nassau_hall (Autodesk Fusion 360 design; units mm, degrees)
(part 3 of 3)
sketch "Sketch80" plane through (0, 0, -14.3624) normal (0, 0, -1) x axis (1, 0, 0)
  line L1 (-39, 78) -> (-39, 61)
  line L2 (32, 78) -> (-39, 78)
  line L3 (32, 61) -> (32, 78)
  line L4 (33.9524, 61) -> (32, 61)
  line L5 (33.9524, 61.1302) -> (33.9524, 61)
  line L6 (157.9638, 61.1302) -> (33.9524, 61.1302)
  line L7 (157.9638, -17.1616) -> (157.9638, 61.1302)
  line L8 (33.9524, -17.1616) -> (157.9638, -17.1616)
  line L9 (33.9524, -17.0793) -> (33.9524, -17.1616)
  line L10 (32, -17.0793) -> (33.9524, -17.0793)
  line L11 (32, -55.6025) -> (32, -17.0793)
  line L12 (-38.959, -55.6025) -> (32, -55.6025)
  line L13 (-38.959, -19) -> (-38.959, -55.6025)
  line L14 (-39.0985, -19) -> (-38.959, -19)
  line L15 (-39.0985, -17.0793) -> (-39.0985, -19)
  line L16 (-41.0476, -17.0793) -> (-39.0985, -17.0793)
  line L17 (-41.0476, -57.3945) -> (-41.0476, -17.0793)
  line L18 (33.9524, -57.3945) -> (-41.0476, -57.3945)
  line L19 (33.9524, -32.3945) -> (33.9524, -57.3945)
  line L20 (160.4524, -32.3945) -> (33.9524, -32.3945)
  line L21 (160.4524, 63.1055) -> (160.4524, -32.3945)
  line L22 (33.9524, 63.1055) -> (160.4524, 63.1055)
  line L23 (33.9524, 80.1055) -> (33.9524, 63.1055)
  line L24 (-41.0476, 80.1055) -> (33.9524, 80.1055)
  line L25 (-41.0476, 61) -> (-41.0476, 80.1055)
  line L26 (-39, 61) -> (-41.0476, 61)
  line L27 (33.9524, -17.0793) -> (32, -17.0793)
  line L28 (33.9524, -30.8511) -> (33.9524, -17.0793)
  line L29 (32, -30.8511) -> (33.9524, -30.8511)
  line L30 (32, -17.0793) -> (32, -30.8511)
  point P12 (32, -17.0793)
  point P28 (32, -17.0793)
  horizontal L27
  vertical L28
  horizontal L29
  vertical L30
  coincident P12 P28
extrude "Extrude54" cut sketch "Sketch80" profile of L9 L10 L11 L27 L28 L29 L30 against normal blind 70
sketch "Sketch81" plane through (0, 0, -14.3624) normal (0, 0, -1) x axis (1, 0, 0)
  line L1 (32, -30.8511) -> (33.9524, -30.8511)
  line L2 (32, -55.6025) -> (32, -30.8511)
  line L3 (-38.959, -55.6025) -> (32, -55.6025)
  line L4 (-38.959, -19) -> (-38.959, -55.6025)
  line L5 (-39.0985, -19) -> (-38.959, -19)
  line L6 (-39.0985, -17.0793) -> (-39.0985, -19)
  line L7 (-41.0476, -17.0793) -> (-39.0985, -17.0793)
  line L8 (-41.0476, -57.3945) -> (-41.0476, -17.0793)
  line L9 (33.9524, -57.3945) -> (-41.0476, -57.3945)
  line L10 (33.9524, -32.3945) -> (33.9524, -57.3945)
  line L11 (160.4524, -32.3945) -> (33.9524, -32.3945)
  line L12 (160.4524, 63.1055) -> (160.4524, -32.3945)
  line L13 (33.9524, 63.1055) -> (160.4524, 63.1055)
  line L14 (33.9524, 80.1055) -> (33.9524, 63.1055)
  line L15 (-41.0476, 80.1055) -> (33.9524, 80.1055)
  line L16 (-41.0476, 61) -> (-41.0476, 80.1055)
  line L17 (-39, 61) -> (-41.0476, 61)
  line L18 (-39, 78) -> (-39, 61)
  line L19 (32, 78) -> (-39, 78)
  line L20 (32, 61) -> (32, 78)
  line L21 (33.9524, 61) -> (32, 61)
  line L22 (33.9524, 61.1302) -> (33.9524, 61)
  line L23 (157.9638, 61.1302) -> (33.9524, 61.1302)
  line L24 (157.9638, -17.1616) -> (157.9638, 61.1302)
  line L25 (33.9524, -17.1616) -> (157.9638, -17.1616)
  line L26 (33.9524, -30.8511) -> (33.9524, -17.1616)
  line L27 (157.9638, -30.8511) -> (33.9524, -30.8511)
  line L28 (157.9638, -17.1616) -> (157.9638, -30.8511)
  line L29 (33.9524, -17.1616) -> (157.9638, -17.1616)
  line L30 (33.9524, -30.8511) -> (33.9524, -17.1616)
  point P26 (157.9638, -17.1616)
  point P30 (157.9638, -17.1616)
  point P2 (33.9524, -30.8511)
  point P28 (33.9524, -30.8511)
  horizontal L27
  vertical L28
  horizontal L29
  vertical L30
  coincident P26 P30
  coincident P2 P28
extrude "Extrude55" cut sketch "Sketch81" profile of L25 L26 L27 L28 L29 L30 against normal blind 70
extrude "Extrude56" add of existing geometry blind 12
sketch "Sketch82" plane through (0, 0, -14.3624) normal (0, 0, -1) x axis (1, 0, 0)
  line L1 (-39, 61) -> (-166, 61)
  line L2 (-39, 78) -> (-39, 61)
  line L3 (32, 78) -> (-39, 78)
  line L4 (32, 61) -> (32, 78)
  line L5 (33.9524, 61) -> (32, 61)
  line L6 (33.9524, 61.1302) -> (33.9524, 61)
  line L7 (157.9638, 61.1302) -> (33.9524, 61.1302)
  line L8 (157.9638, -30.8511) -> (157.9638, 61.1302)
  line L9 (32, -30.8511) -> (157.9638, -30.8511)
  line L10 (32, -55.6025) -> (32, -30.8511)
  line L11 (-38.959, -55.6025) -> (32, -55.6025)
  line L12 (-38.959, -19) -> (-38.959, -55.6025)
  line L13 (-39.0985, -19) -> (-38.959, -19)
  line L14 (-39.0985, -17.0793) -> (-39.0985, -19)
  line L15 (-41.0476, -17.0793) -> (-39.0985, -17.0793)
  line L16 (-41.0476, -17.2714) -> (-41.0476, -17.0793)
  line L17 (-43, -17.2714) -> (-41.0476, -17.2714)
  line L18 (-43, -18) -> (-43, -17.2714)
  line L19 (-166, -18) -> (-43, -18)
  line L20 (-166, 61) -> (-166, -18)
  line L21 (-167.5476, 63.1055) -> (-41.0476, 63.1055)
  line L22 (-167.5476, -31.3945) -> (-167.5476, 63.1055)
  line L23 (-41.0476, -31.3945) -> (-167.5476, -31.3945)
  line L24 (-41.0476, -57.3945) -> (-41.0476, -31.3945)
  line L25 (33.9524, -57.3945) -> (-41.0476, -57.3945)
  line L26 (33.9524, -32.3945) -> (33.9524, -57.3945)
  line L27 (160.4524, -32.3945) -> (33.9524, -32.3945)
  line L28 (160.4524, 63.1055) -> (160.4524, -32.3945)
  line L29 (33.9524, 63.1055) -> (160.4524, 63.1055)
  line L30 (33.9524, 80.1055) -> (33.9524, 63.1055)
  line L31 (-41.0476, 80.1055) -> (33.9524, 80.1055)
  line L32 (-41.0476, 63.1055) -> (-41.0476, 80.1055)
  line L33 (-166, -18) -> (-43, -18)
  line L34 (-166, -30) -> (-166, -18)
  line L35 (-43, -30) -> (-166, -30)
  line L36 (-43, -18) -> (-43, -30)
  point P20 (-43, -18)
  point P34 (-43, -18)
  horizontal L33
  vertical L34
  horizontal L35
  vertical L36
  coincident P20 P34
extrude "Extrude57" cut sketch "Sketch82" profile of L19 L33 L34 L35 L36 against normal blind 70
sketch "Sketch83" plane through (0, 0, -14.3624) normal (0, 0, -1) x axis (1, 0, 0)
  line L1 (-167.5476, 63.1055) -> (-41.0476, 63.1055)
  line L2 (-167.5476, -31.3945) -> (-167.5476, 63.1055)
  line L3 (-41.0476, -31.3945) -> (-167.5476, -31.3945)
  line L4 (-41.0476, -57.3945) -> (-41.0476, -31.3945)
  line L5 (33.9524, -57.3945) -> (-41.0476, -57.3945)
  line L6 (33.9524, -32.3945) -> (33.9524, -57.3945)
  line L7 (160.4524, -32.3945) -> (33.9524, -32.3945)
  line L8 (160.4524, 63.1055) -> (160.4524, -32.3945)
  line L9 (33.9524, 63.1055) -> (160.4524, 63.1055)
  line L10 (33.9524, 80.1055) -> (33.9524, 63.1055)
  line L11 (-41.0476, 80.1055) -> (33.9524, 80.1055)
  line L12 (-41.0476, 63.1055) -> (-41.0476, 80.1055)
  line L13 (-43, -30) -> (-43, -17.2714)
  line L14 (-166, -30) -> (-43, -30)
  line L15 (-166, 61) -> (-166, -30)
  line L16 (-39, 61) -> (-166, 61)
  line L17 (-39, 78) -> (-39, 61)
  line L18 (32, 78) -> (-39, 78)
  line L19 (32, 61) -> (32, 78)
  line L20 (33.9524, 61) -> (32, 61)
  line L21 (33.9524, 61.1302) -> (33.9524, 61)
  line L22 (157.9638, 61.1302) -> (33.9524, 61.1302)
  line L23 (157.9638, -30.8511) -> (157.9638, 61.1302)
  line L24 (32, -30.8511) -> (157.9638, -30.8511)
  line L25 (32, -55.6025) -> (32, -30.8511)
  line L26 (-38.959, -55.6025) -> (32, -55.6025)
  line L27 (-38.959, -19) -> (-38.959, -55.6025)
  line L28 (-39.0985, -19) -> (-38.959, -19)
  line L29 (-39.0985, -17.0793) -> (-39.0985, -19)
  line L30 (-41.0476, -17.0793) -> (-39.0985, -17.0793)
  line L31 (-41.0476, -17.2714) -> (-41.0476, -17.0793)
  line L32 (-43, -17.2714) -> (-41.0476, -17.2714)
  line L33 (-39.0985, -17.0793) -> (-41.0476, -17.0793)
  line L34 (-39.0985, -30.309) -> (-39.0985, -17.0793)
  line L35 (-41.0476, -30.309) -> (-39.0985, -30.309)
  line L36 (-41.0476, -17.0793) -> (-41.0476, -30.309)
  point P32 (-41.0476, -17.0793)
  point P34 (-41.0476, -17.0793)
  horizontal L33
  vertical L34
  horizontal L35
  vertical L36
  coincident P32 P34
extrude "Extrude58" cut sketch "Sketch83" profile of L29 L30 L31 L33 L34 L35 L36 against normal blind 70
sketch "Sketch84" plane through (0, 0, -14.3624) normal (0, 0, -1) x axis (1, 0, 0)
  line L1 (-39.0985, -30.309) -> (-39.0985, -19)
  line L2 (-41.0476, -30.309) -> (-39.0985, -30.309)
  line L3 (-41.0476, -17.2714) -> (-41.0476, -30.309)
  line L4 (-43, -17.2714) -> (-41.0476, -17.2714)
  line L5 (-43, -30) -> (-43, -17.2714)
  line L6 (-166, -30) -> (-43, -30)
  line L7 (-166, 61) -> (-166, -30)
  line L8 (-39, 61) -> (-166, 61)
  line L9 (-39, 78) -> (-39, 61)
  line L10 (32, 78) -> (-39, 78)
  line L11 (32, 61) -> (32, 78)
  line L12 (33.9524, 61) -> (32, 61)
  line L13 (33.9524, 61.1302) -> (33.9524, 61)
  line L14 (157.9638, 61.1302) -> (33.9524, 61.1302)
  line L15 (157.9638, -30.8511) -> (157.9638, 61.1302)
  line L16 (32, -30.8511) -> (157.9638, -30.8511)
  line L17 (32, -55.6025) -> (32, -30.8511)
  line L18 (-38.959, -55.6025) -> (32, -55.6025)
  line L19 (-38.959, -19) -> (-38.959, -55.6025)
  line L20 (-39.0985, -19) -> (-38.959, -19)
  line L21 (-167.5476, 63.1055) -> (-41.0476, 63.1055)
  line L22 (-167.5476, -31.3945) -> (-167.5476, 63.1055)
  line L23 (-41.0476, -31.3945) -> (-167.5476, -31.3945)
  line L24 (-41.0476, -57.3945) -> (-41.0476, -31.3945)
  line L25 (33.9524, -57.3945) -> (-41.0476, -57.3945)
  line L26 (33.9524, -32.3945) -> (33.9524, -57.3945)
  line L27 (160.4524, -32.3945) -> (33.9524, -32.3945)
  line L28 (160.4524, 63.1055) -> (160.4524, -32.3945)
  line L29 (33.9524, 63.1055) -> (160.4524, 63.1055)
  line L30 (33.9524, 80.1055) -> (33.9524, 63.1055)
  line L31 (-41.0476, 80.1055) -> (33.9524, 80.1055)
  line L32 (-41.0476, 63.1055) -> (-41.0476, 80.1055)
  line L33 (-41.0476, -17.2714) -> (-43, -17.2714)
  line L34 (-41.0476, -30.0185) -> (-41.0476, -17.2714)
  line L35 (-43, -30.0185) -> (-41.0476, -30.0185)
  line L36 (-43, -17.2714) -> (-43, -30.0185)
  point P36 (-41.0476, -30.0185)
  point P6 (-43, -17.2714)
  point P34 (-43, -17.2714)
  horizontal L33
  vertical L34
  horizontal L35
  vertical L36
  coincident L3 P36
  coincident P6 P34
extrude "Extrude59" cut sketch "Sketch84" profile of L3 L4 L5 L33 L34 L35 L36 against normal blind 70
sketch "Sketch85" plane through (0, 0, 55.6376) normal (0, 0, -1) x axis (1, 0, 0)
  line L1 (-166, -30.2) -> (-38.9574, -30.3224)
  line L2 (-165.9998, -30.0065) -> (-166, -30.2)
  perpendicular L1 L2
sketch "Sketch86" plane through (0, 0, -14.3624) normal (0, 0, -1) x axis (1, 0, 0)
  line L1 (-167.5476, 63.1055) -> (-41.0476, 63.1055)
  line L2 (-167.5476, -31.3945) -> (-167.5476, 63.1055)
  line L3 (-41.0476, -31.3945) -> (-167.5476, -31.3945)
  line L4 (-41.0476, -57.3945) -> (-41.0476, -31.3945)
  line L5 (33.9524, -57.3945) -> (-41.0476, -57.3945)
  line L6 (33.9524, -32.3945) -> (33.9524, -57.3945)
  line L7 (160.4524, -32.3945) -> (33.9524, -32.3945)
  line L8 (160.4524, 63.1055) -> (160.4524, -32.3945)
  line L9 (33.9524, 63.1055) -> (160.4524, 63.1055)
  line L10 (33.9524, 80.1055) -> (33.9524, 63.1055)
  line L11 (-41.0476, 80.1055) -> (33.9524, 80.1055)
  line L12 (-41.0476, 63.1055) -> (-41.0476, 80.1055)
  line L13 (-43, -30.0185) -> (-41.0476, -30.0185)
  line L14 (-43, -30) -> (-43, -30.0185)
  line L15 (-166, -30) -> (-43, -30)
  line L16 (-166, 61) -> (-166, -30)
  line L17 (-39, 61) -> (-166, 61)
  line L18 (-39, 78) -> (-39, 61)
  line L19 (32, 78) -> (-39, 78)
  line L20 (32, 61) -> (32, 78)
  line L21 (33.9524, 61) -> (32, 61)
  line L22 (33.9524, 61.1302) -> (33.9524, 61)
  line L23 (157.9638, 61.1302) -> (33.9524, 61.1302)
  line L24 (157.9638, -30.8511) -> (157.9638, 61.1302)
  line L25 (32, -30.8511) -> (157.9638, -30.8511)
  line L26 (32, -55.6025) -> (32, -30.8511)
  line L27 (-38.959, -55.6025) -> (32, -55.6025)
  line L28 (-38.959, -19) -> (-38.959, -55.6025)
  line L29 (-39.0985, -19) -> (-38.959, -19)
  line L30 (-39.0985, -30.309) -> (-39.0985, -19)
  line L31 (-41.0476, -30.309) -> (-39.0985, -30.309)
  line L32 (-41.0476, -30.0185) -> (-41.0476, -30.309)
  line L33 (-39.0985, -30.309) -> (-38.959, -30.309)
  point P34 (-38.959, -30.309)
  point P32 (-39.0985, -30.309)
  point P35 (-39.0985, -30.309)
  coincident L28 P34
  coincident P32 P35
  perpendicular L30 L33
extrude "Extrude60" cut sketch "Sketch86" profile of L28 L29 L30 L33 against normal blind 70
sphere_primitive "SpherePrimitive5" Diameter 3
move_face "MoveFace17"
move_face "MoveFace18"
move_face "MoveFace19"
move "Move34"
move "Move35"
move "Move36"
move_face "MoveFace20"
move "Move37"
move "Move38"
move_face "MoveFace21"
offset_faces "OffsetFaces1" distance -0.5
delete_face "DeleteFace6"
combine "Combine1"
extrude "Extrude61" add of existing geometry blind 3
extrude "Extrude62" add of existing geometry blind 4
extrude "Extrude63" add of existing geometry blind 7
extrude "Extrude64" add sketch "Sketch51" along normal blind 7
extrude "Extrude65" add of existing geometry blind 2
extrude "Extrude66" add of existing geometry blind 9
extrude "Extrude67" cut of existing geometry blind -2
extrude "Extrude68" add of existing geometry blind 7
extrude "Extrude69" add of existing geometry blind 7
extrude "Extrude70" add of existing geometry blind 7
extrude "Extrude71" add of existing geometry blind 7
extrude "Extrude72" add of existing geometry blind 7
extrude "Extrude73" add of existing geometry blind -7.414
extrude "Extrude74" add of existing geometry blind 0.3
extrude "Extrude75" add of existing geometry blind 7
extrude "Extrude76" add of existing geometry blind 7
extrude "Extrude77" add of existing geometry blind 7
extrude "Extrude78" add of existing geometry blind 7
extrude "Extrude79" add of existing geometry blind 7
extrude "Extrude80" add of existing geometry blind 7
extrude "Extrude81" add of existing geometry blind 1.975
extrude "Extrude82" cut of existing geometry blind -40
extrude "Extrude83" cut of existing geometry blind -3
extrude "Extrude84" cut of existing geometry blind -3
extrude "Extrude85" cut of existing geometry blind -3
extrude "Extrude86" cut of existing geometry blind -3
extrude "Extrude87" cut of existing geometry blind -3
extrude "Extrude88" cut of existing geometry blind -3
extrude "Extrude89" cut of existing geometry blind -3
extrude "Extrude90" cut of existing geometry blind -3
extrude "Extrude91" cut of existing geometry blind -3
extrude "Extrude92" cut of existing geometry blind -3
extrude "Extrude93" cut of existing geometry blind -3
extrude "Extrude94" cut of existing geometry blind -3
extrude "Extrude95" cut of existing geometry blind -3
extrude "Extrude96" cut of existing geometry blind -3
sketch "Sketch88" plane through (-167.5476, 0, 0) normal (-1, 0, 0) x axis (0, -1, 0)
  line L1 (21.5, -6) -> (21.5, 3)
  line L2 (17, -6) -> (21.5, -6)
  line L3 (17, 3) -> (17, -6)
  line L4 (21.5, 3) -> (17, 3)
  line L5 (6.5, -6) -> (6.5, 3)
  line L6 (2, -6) -> (6.5, -6)
  line L7 (2, 3) -> (2, -6)
  line L8 (6.5, 3) -> (2, 3)
  line L9 (51.5, 38) -> (51.5, 45)
  line L10 (47, 38) -> (51.5, 38)
  line L11 (47, 45) -> (47, 38)
  line L12 (51.5, 45) -> (47, 45)
  line L13 (6.5, 17) -> (6.5, 26)
  line L14 (2, 17) -> (6.5, 17)
  line L15 (2, 26) -> (2, 17)
  line L16 (6.5, 26) -> (2, 26)
  line L17 (-8.5, 17) -> (-8.5, 26)
  line L18 (-13, 17) -> (-8.5, 17)
  line L19 (-13, 26) -> (-13, 17)
  line L20 (-8.5, 26) -> (-13, 26)
  line L21 (51.5, 17) -> (51.5, 26)
  line L22 (47, 17) -> (51.5, 17)
  line L23 (47, 26) -> (47, 17)
  line L24 (51.5, 26) -> (47, 26)
  line L25 (6.5, 38) -> (6.5, 45)
  line L26 (2, 38) -> (6.5, 38)
  line L27 (2, 45) -> (2, 38)
  line L28 (6.5, 45) -> (2, 45)
  line L29 (36.5, 38) -> (36.5, 45)
  line L30 (32, 38) -> (36.5, 38)
  line L31 (32, 45) -> (32, 38)
  line L32 (36.5, 45) -> (32, 45)
  line L33 (21.5, 17) -> (21.5, 26)
  line L34 (17, 17) -> (21.5, 17)
  line L35 (17, 26) -> (17, 17)
  line L36 (21.5, 26) -> (17, 26)
  line L37 (-8.5, 38) -> (-8.5, 45)
  line L38 (-13, 38) -> (-8.5, 38)
  line L39 (-13, 45) -> (-13, 38)
  line L40 (-8.5, 45) -> (-13, 45)
  line L41 (36.5, 17) -> (36.5, 26)
  line L42 (32, 17) -> (36.5, 17)
  line L43 (32, 26) -> (32, 17)
  line L44 (36.5, 26) -> (32, 26)
  line L45 (21.5, 38) -> (21.5, 45)
  line L46 (17, 38) -> (21.5, 38)
  line L47 (17, 45) -> (17, 38)
  line L48 (21.5, 45) -> (17, 45)
  line L49 (36.5, -6) -> (36.5, 3)
  line L50 (32, -6) -> (36.5, -6)
  line L51 (32, 3) -> (32, -6)
  line L52 (36.5, 3) -> (32, 3)
  line L53 (-8.5, -6) -> (-8.5, 3)
  line L54 (-13, -6) -> (-8.5, -6)
  line L55 (-13, 3) -> (-13, -6)
  line L56 (-8.5, 3) -> (-13, 3)
  line L57 (51.5, -6) -> (51.5, 3)
  line L58 (47, -6) -> (51.5, -6)
  line L59 (47, 3) -> (47, -6)
  line L60 (51.5, 3) -> (47, 3)
  line L61 (63.1055, -14.3624) -> (-31.3945, -14.3624)
  line L62 (63.1055, 55.1376) -> (63.1055, -14.3624)
  line L63 (-31.3945, 55.1376) -> (63.1055, 55.1376)
  line L64 (-31.3945, -14.3624) -> (-31.3945, 55.1376)
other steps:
base_feature "Base Feature1"
extrude "Extrude34" cut sketch "Sketch28" profile of L5 L6 L7 L8 against normal blind 70
extrude "Extrude42" cut of existing geometry blind -200
extrude "Extrude47" cut of existing geometry blind -500
extrude "Extrude48" cut of existing geometry blind -500
extrude "Extrude49" cut of existing geometry blind -500
extrude "Extrude50" cut of existing geometry blind -500
create_component "CreateComponent1"
create_component "CreateComponent9"
remove_body "RemoveBody1"
remove_body "RemoveBody2"
remove_body "RemoveBody3"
